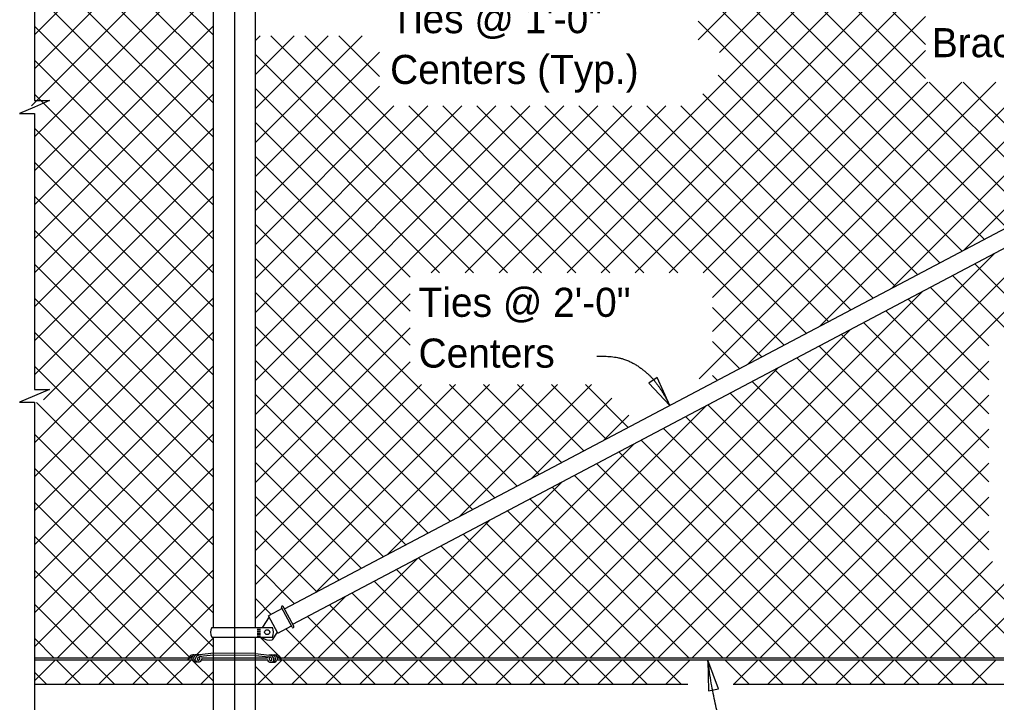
# Model space of a CAD drawing. Extents: x 0.5 to 39.7, y 0.9 to 25.6.
# Drawn here: x 0.72 to 7.49, y 17.01 to 21.74 of the extents above; entities that cross this region are included whole.
import ezdxf

# ---------------------------------------------------------------- set-up
doc = ezdxf.new("R2010")
doc.units = 0
for name, color, linetype in [('CL_Major', 7, 'Continuous'), ('Dimension', 7, 'Continuous'), ('Miscellaneous', 7, 'Continuous'), ('SteelMisc', 7, 'Continuous'), ('SteelMisc_h', 7, 'Continuous'), ('SupstrConc', 7, 'Continuous'), ('TextStructures', 7, 'Continuous')]:
    doc.layers.add(name, color=color, linetype=linetype)

msp = doc.modelspace()

# ---------------------------------------------------------------- linework, layer by layer
at = {"layer": 'CL_Major'}
msp.add_line((2.2062, 25.5043), (2.2062, 14.6639), dxfattribs=at)
at = {"layer": 'Dimension'}
for points in [[(0.8194, 23.1382), (0.8194, 21.1819), (0.9227, 21.1819), (0.8194, 21.1369), (0.716, 21.0919), (0.8194, 21.0919), (0.8194, 20.1983)], [(0.8194, 20.1983), (0.8194, 19.1806), (0.9227, 19.1806), (0.8194, 19.1356), (0.716, 19.0906), (0.8194, 19.0906), (0.8194, 16.8862)], [(0.8194, 17.1362), (0.8194, 15.2854), (0.9227, 15.2854), (0.8194, 15.2404), (0.716, 15.1954), (0.8194, 15.1954), (0.8194, 13.3576)]]:
    msp.add_lwpolyline(points, dxfattribs=at)
for points in [[(5.2237, 19.0693), (5.1367, 19.2617), (5.0782, 19.2224)], [(5.4878, 17.3029), (5.4928, 17.0917), (5.5621, 17.1051)]]:
    msp.add_lwpolyline(points, close=True, dxfattribs=at)
for points in [[(4.7176, 19.4097), (4.8713, 19.4171), (5.0618, 19.3098), (5.1749, 19.1668), (5.2237, 19.0692)], [(6.1508, 16.5088), (5.753, 16.5088), (5.549, 16.8458), (5.4877, 17.3027)]]:
    msp.add_open_spline(points, degree=2, dxfattribs=at)
at = {"layer": 'Miscellaneous'}
for p, q in [((7.2429, 22.9547), (4.2774, 19.9892)), ((7.2492, 20.1396), (4.4341, 22.9547)), ((7.4786, 22.9547), (4.5131, 19.9892)), ((7.4034, 20.2211), (4.6698, 22.9547)), ((7.7143, 22.9547), (4.7488, 19.9892)), ((7.5576, 20.3026), (4.9055, 22.9547)), ((7.95, 22.9547), (4.9845, 19.9892)), ((7.7118, 20.3841), (5.1412, 22.9547)), ((6.9957, 21.336), (5.377, 22.9547)), ((6.7715, 22.9547), (5.4205, 21.6037)), ((7.0072, 22.9547), (5.5678, 21.5153)), ((6.9957, 21.5717), (5.6127, 22.9547)), ((2.0603, 22.8796), (0.8192, 21.6385)), ((2.0603, 21.6353), (0.8192, 22.8764)), ((2.0603, 22.6439), (0.8192, 21.4028)), ((2.0603, 21.3996), (0.8192, 22.6407)), ((2.0603, 22.4082), (0.7982, 21.146)), ((2.0603, 21.1639), (0.8192, 22.405)), ((2.0603, 22.1725), (0.8192, 20.9314)), ((2.0603, 20.9282), (0.8192, 22.1693)), ((2.0603, 21.9368), (0.8192, 20.6957)), ((2.0603, 20.6925), (0.8192, 21.9336)), ((6.9957, 21.7647), (5.2202, 19.9892)), ((2.0603, 21.701), (0.8192, 20.46)), ((2.0603, 20.4568), (0.8192, 21.6979)), ((7.095, 20.0581), (5.4205, 21.7327)), ((2.6187, 21.6304), (2.352, 21.3636)), ((2.383, 21.6304), (2.352, 21.5993)), ((2.8544, 21.6304), (2.352, 21.1279)), ((3.0901, 21.6304), (2.352, 20.8922)), ((4.0998, 19.9892), (2.4587, 21.6304)), ((4.3355, 19.9892), (2.6944, 21.6304)), ((3.2122, 21.3482), (2.9301, 21.6304)), ((3.2122, 21.5167), (2.352, 20.6565)), ((3.8641, 19.9892), (2.352, 21.5013)), ((6.9957, 21.529), (5.4559, 19.9892)), ((2.0603, 21.4653), (0.8192, 20.2243)), ((2.0603, 20.2211), (0.8192, 21.4622)), ((6.9408, 19.9766), (5.559, 21.3585)), ((3.2122, 21.281), (2.352, 20.4208)), ((3.6284, 19.9892), (2.352, 21.2656)), ((7.4843, 21.3105), (5.4275, 19.2537)), ((7.0129, 21.3105), (5.5188, 19.8164)), ((7.2486, 21.3105), (5.5188, 19.5807)), ((7.72, 21.3105), (5.7646, 19.3551)), ((7.9557, 21.3105), (6.2644, 19.6192)), ((8.1914, 21.3105), (6.7643, 19.8834)), ((7.8661, 20.4656), (7.0212, 21.3105)), ((8.0203, 20.5471), (7.2569, 21.3105)), ((8.4271, 21.3105), (7.2641, 20.1475)), ((2.0603, 21.2296), (0.8192, 19.9886)), ((2.0603, 19.9854), (0.8192, 21.2265)), ((6.7866, 19.8952), (5.4525, 21.2292)), ((4.2544, 21.1447), (2.352, 19.2423)), ((3.783, 21.1447), (2.352, 19.7137)), ((3.3116, 21.1447), (2.352, 20.1851)), ((3.5473, 21.1447), (2.352, 19.9494)), ((4.0187, 21.1447), (2.352, 19.478)), ((4.4901, 21.1447), (2.352, 19.0066)), ((4.5712, 19.9892), (3.4157, 21.1447)), ((4.7258, 21.1447), (3.5703, 19.9892)), ((4.8069, 19.9892), (3.6514, 21.1447)), ((4.9615, 21.1447), (3.806, 19.9892)), ((5.0426, 19.9892), (3.8871, 21.1447)), ((5.1972, 21.1447), (4.0417, 19.9892)), ((5.2783, 19.9892), (4.1228, 21.1447)), ((6.0155, 19.4877), (4.3585, 21.1447)), ((6.1697, 19.5692), (4.5942, 21.1447)), ((6.324, 19.6507), (4.8299, 21.1447)), ((6.4782, 19.7322), (5.0656, 21.1447)), ((6.6324, 19.8137), (5.3013, 21.1447)), ((2.0603, 20.9939), (0.8192, 19.7529)), ((3.4233, 19.9586), (2.352, 21.0299)), ((2.0603, 19.7497), (0.8192, 20.9908)), ((3.4233, 19.7229), (2.352, 20.7942)), ((2.0603, 20.7582), (0.8192, 19.5171)), ((2.0603, 19.514), (0.8192, 20.7551)), ((8.4761, 20.6523), (5.1412, 17.3175)), ((2.0603, 20.5225), (0.8192, 19.2814)), ((3.4233, 19.4872), (2.352, 20.5585)), ((2.0603, 19.2783), (0.8192, 20.5194)), ((7.9762, 20.3882), (4.9055, 17.3175)), ((4.165, 18.5098), (2.352, 20.3228)), ((2.0603, 19.0426), (0.8192, 20.2837)), ((2.0603, 20.2868), (0.8817, 19.1083)), ((7.4764, 20.1241), (4.6698, 17.3175)), ((2.0603, 20.0511), (0.8192, 18.81)), ((2.0603, 18.8069), (0.8192, 20.048)), ((4.0108, 18.4283), (2.352, 20.0871)), ((7.8655, 19.5233), (7.3379, 20.0509)), ((7.6298, 19.5233), (7.1837, 19.9694)), ((3.8566, 18.3468), (2.352, 19.8514)), ((6.9765, 19.8599), (4.4341, 17.3175)), ((7.4353, 19.4821), (7.0295, 19.8879)), ((2.0603, 19.8154), (0.8192, 18.5743)), ((2.0603, 18.5712), (0.8192, 19.8123)), ((3.4233, 19.8423), (2.352, 18.7709)), ((7.4353, 19.2464), (6.8753, 19.8064)), ((5.8613, 19.4062), (5.5188, 19.7488)), ((7.4353, 19.0107), (6.7211, 19.7249)), ((7.4353, 18.775), (6.5669, 19.6435)), ((2.0603, 19.5797), (0.8192, 18.3386)), ((2.0603, 18.3355), (0.8192, 19.5766)), ((3.7024, 18.2653), (2.352, 19.6157)), ((3.4233, 19.6066), (2.352, 18.5352)), ((6.4767, 19.5958), (4.1984, 17.3175)), ((5.7071, 19.3247), (5.5188, 19.5131)), ((7.4353, 18.5393), (6.4127, 19.562)), ((7.4353, 18.3036), (6.2585, 19.4805)), ((3.5482, 18.1838), (2.352, 19.38)), ((3.4233, 19.3709), (2.352, 18.2995)), ((7.4353, 19.3759), (5.377, 17.3175)), ((7.4353, 18.0679), (6.1042, 19.399)), ((2.0603, 19.344), (0.8192, 18.1029)), ((2.0603, 18.0998), (0.8192, 19.3409)), ((5.9769, 19.3317), (3.9627, 17.3175)), ((7.95, 17.3175), (5.95, 19.3175)), ((5.5529, 19.2432), (5.5188, 19.2774)), ((7.7143, 17.3175), (5.7958, 19.236)), ((3.7384, 19.2146), (2.352, 17.8281)), ((3.5027, 19.2146), (2.352, 18.0638)), ((3.9741, 19.2146), (2.352, 17.5924)), ((4.2098, 19.2146), (2.7654, 17.7701)), ((4.4455, 19.2146), (3.2653, 18.0343)), ((4.3192, 18.5913), (3.6959, 19.2146)), ((4.6812, 19.2146), (3.7651, 18.2985)), ((4.4734, 18.6728), (3.9317, 19.2146)), ((4.6277, 18.7543), (4.1674, 19.2146)), ((4.7819, 18.8357), (4.4031, 19.2146)), ((4.9361, 18.9172), (4.6388, 19.2146)), ((2.0603, 19.1083), (0.8192, 17.8672)), ((3.394, 18.1023), (2.352, 19.1443)), ((4.8227, 19.1203), (4.265, 18.5626)), ((7.4353, 19.1402), (5.6127, 17.3175)), ((7.4786, 17.3175), (5.6416, 19.1545)), ((2.0603, 17.8641), (0.8339, 19.0905)), ((5.477, 19.0675), (3.727, 17.3175)), ((7.2429, 17.3175), (5.4874, 19.073)), ((4.9405, 19.0024), (4.7648, 18.8268)), ((7.0072, 17.3175), (5.3332, 18.9915)), ((3.2398, 18.0208), (2.352, 18.9086)), ((6.7715, 17.3175), (5.179, 18.91)), ((7.4353, 18.9045), (5.8484, 17.3175)), ((2.0603, 18.8726), (0.8192, 17.6315)), ((2.0603, 17.6284), (0.8192, 18.8695)), ((6.5358, 17.3175), (5.0248, 18.8285)), ((4.9772, 18.8034), (3.4913, 17.3175)), ((6.3001, 17.3175), (4.8706, 18.747)), ((2.0603, 18.6369), (0.8192, 17.3958)), ((2.0603, 17.3927), (0.8192, 18.6338)), ((3.0856, 17.9393), (2.352, 18.6729)), ((6.0644, 17.3175), (4.7163, 18.6656)), ((7.4353, 18.6688), (6.0841, 17.3175)), ((5.8287, 17.3175), (4.5621, 18.5841)), ((4.4774, 18.5393), (3.2556, 17.3175)), ((5.593, 17.3175), (4.4079, 18.5026)), ((2.9314, 17.8578), (2.352, 18.4372)), ((5.3573, 17.3175), (4.2537, 18.4211)), ((7.4353, 18.4331), (6.3198, 17.3175)), ((1.8909, 17.3264), (0.8192, 18.3981)), ((2.0603, 18.4012), (0.9766, 17.3175)), ((5.1216, 17.3175), (4.0995, 18.3396)), ((3.9775, 18.2751), (3.0199, 17.3175)), ((4.8859, 17.3175), (3.9453, 18.2581)), ((1.6641, 17.3175), (0.8192, 18.1624)), ((2.0603, 18.1655), (1.2123, 17.3175)), ((2.7771, 17.7763), (2.352, 18.2015)), ((4.6502, 17.3175), (3.7911, 18.1766)), ((7.4353, 18.1974), (6.5555, 17.3175)), ((4.4145, 17.3175), (3.6369, 18.0951)), ((2.6229, 17.6948), (2.352, 17.9658)), ((3.4777, 18.011), (2.7842, 17.3175)), ((4.1788, 17.3175), (3.4827, 18.0136)), ((7.4598, 17.9862), (6.7912, 17.3175)), ((7.6955, 17.9862), (7.0269, 17.3175)), ((7.9312, 17.9862), (7.2626, 17.3175)), ((1.4284, 17.3175), (0.8192, 17.9267)), ((2.0603, 17.9298), (1.448, 17.3175)), ((3.943, 17.3175), (3.3285, 17.9321)), ((3.7073, 17.3175), (3.1742, 17.8506)), ((2.9778, 17.7469), (2.5485, 17.3175)), ((3.4716, 17.3175), (3.02, 17.7692)), ((1.1927, 17.3175), (0.8192, 17.691)), ((2.0603, 17.6941), (1.6837, 17.3175)), ((2.4612, 17.6209), (2.352, 17.7301)), ((3.2359, 17.3175), (2.8658, 17.6877)), ((3.0002, 17.3175), (2.7116, 17.6062)), ((2.7645, 17.3175), (2.5621, 17.52)), ((0.957, 17.3175), (0.8192, 17.4553)), ((2.0603, 17.4584), (1.9429, 17.341)), ((2.5129, 17.3335), (2.3833, 17.4631)), ((0.9619, 17.3028), (0.8192, 17.1601)), ((1.1384, 17.1361), (0.9717, 17.3028)), ((1.1976, 17.3028), (1.0309, 17.1361)), ((1.3741, 17.1361), (1.2074, 17.3028)), ((1.4333, 17.3028), (1.2666, 17.1361)), ((1.6098, 17.1361), (1.4431, 17.3028)), ((1.669, 17.3028), (1.5023, 17.1361)), ((1.8455, 17.1361), (1.6788, 17.3028)), ((1.9047, 17.3028), (1.738, 17.1361)), ((2.0603, 17.157), (1.922, 17.2953)), ((2.5338, 17.3028), (2.3671, 17.1361)), ((2.5288, 17.3175), (2.5253, 17.3211)), ((2.7103, 17.1361), (2.5436, 17.3028)), ((2.7695, 17.3028), (2.6028, 17.1361)), ((2.946, 17.1361), (2.7793, 17.3028)), ((3.0052, 17.3028), (2.8385, 17.1361)), ((3.1817, 17.1361), (3.015, 17.3028)), ((3.2409, 17.3028), (3.0742, 17.1361)), ((3.4174, 17.1361), (3.2507, 17.3028)), ((3.4766, 17.3028), (3.3099, 17.1361)), ((3.6531, 17.1361), (3.4864, 17.3028)), ((3.7123, 17.3028), (3.5456, 17.1361)), ((3.8888, 17.1361), (3.7221, 17.3028)), ((3.948, 17.3028), (3.7813, 17.1361)), ((4.1245, 17.1361), (3.9578, 17.3028)), ((4.1837, 17.3028), (4.017, 17.1361)), ((4.3602, 17.1361), (4.1935, 17.3028)), ((4.4194, 17.3028), (4.2527, 17.1361)), ((4.5959, 17.1361), (4.4292, 17.3028)), ((4.6551, 17.3028), (4.4884, 17.1361)), ((4.8316, 17.1361), (4.6649, 17.3028)), ((4.8908, 17.3028), (4.7241, 17.1361)), ((5.0673, 17.1361), (4.9006, 17.3028)), ((5.1265, 17.3028), (4.9598, 17.1361)), ((5.303, 17.1361), (5.1363, 17.3028)), ((5.3622, 17.3028), (5.1955, 17.1361)), ((5.7744, 17.1361), (5.6077, 17.3028)), ((5.8336, 17.3028), (5.6669, 17.1361)), ((6.0101, 17.1361), (5.8434, 17.3028)), ((6.0693, 17.3028), (5.9026, 17.1361)), ((6.2458, 17.1361), (6.0791, 17.3028)), ((6.305, 17.3028), (6.1383, 17.1361)), ((6.4815, 17.1361), (6.3148, 17.3028)), ((6.5407, 17.3028), (6.374, 17.1361)), ((6.7172, 17.1361), (6.5505, 17.3028)), ((6.7764, 17.3028), (6.6097, 17.1361)), ((6.9529, 17.1361), (6.7862, 17.3028)), ((7.0121, 17.3028), (6.8455, 17.1361)), ((7.1886, 17.1361), (7.0219, 17.3028)), ((7.2478, 17.3028), (7.0812, 17.1361)), ((7.4243, 17.1361), (7.2576, 17.3028)), ((7.4835, 17.3028), (7.3169, 17.1361)), ((0.9027, 17.1361), (0.8192, 17.2196)), ((2.0571, 17.2195), (1.9737, 17.1361)), ((2.4746, 17.1361), (2.352, 17.2587))]:
    msp.add_line(p, q, dxfattribs=at)
at = {"layer": 'SteelMisc'}
for p, q in [((2.0603, 17.5309), (2.0603, 23.1761)), ((2.352, 17.5309), (2.352, 23.1761)), ((2.5536, 17.6582), (11.8032, 22.5462)), ((2.6095, 17.5522), (11.8592, 22.4401)), ((2.5369, 17.6609), (2.4426, 17.6111)), ((2.5063, 17.4905), (2.4426, 17.6111)), ((2.6052, 17.5317), (2.5328, 17.6688)), ((2.6171, 17.538), (2.5446, 17.6751)), ((2.4468, 17.6031), (2.3999, 17.5313)), ((2.5063, 17.4905), (2.6006, 17.5404)), ((2.049, 17.5309), (2.4687, 17.5309)), ((2.3864, 17.5246), (2.3629, 17.5246)), ((2.3864, 17.5148), (2.3629, 17.5148)), ((2.3864, 17.5031), (2.3629, 17.5031)), ((2.3864, 17.4913), (2.3629, 17.4913)), ((2.3864, 17.4805), (2.3629, 17.4805)), ((2.5029, 17.4971), (2.4681, 17.4439)), ((2.0491, 17.4631), (2.4687, 17.4631)), ((2.0603, 16.801), (2.0603, 17.4631)), ((2.352, 16.801), (2.352, 17.4631)), ((2.3864, 17.4709), (2.3629, 17.4709)), ((2.0608, 17.3518), (1.9665, 17.3407)), ((2.0608, 17.3373), (1.9687, 17.3279)), ((2.352, 17.3501), (2.0608, 17.3518)), ((2.352, 17.3356), (2.0608, 17.3373)), ((2.352, 17.3501), (2.4469, 17.339)), ((1.8859, 17.3175), (0.8192, 17.3175)), ((1.9154, 17.3028), (0.8192, 17.3028)), ((1.9096, 17.3175), (1.8943, 17.3175)), ((2.0603, 17.3028), (1.9773, 17.3028)), ((2.0603, 17.3175), (1.9799, 17.3175)), ((2.352, 17.3356), (2.4446, 17.3261)), ((2.4342, 17.3175), (2.352, 17.3175)), ((2.4356, 17.3028), (2.352, 17.3028)), ((11.8982, 17.3028), (2.5005, 17.3028)), ((2.5172, 17.3175), (2.5041, 17.3175)), ((11.8969, 17.3175), (2.5271, 17.3175))]:
    msp.add_line(p, q, dxfattribs=at)
for centre, start, end in [((2.5385, 17.6721), 27.85098, 207.85098), ((2.611, 17.5349), 207.85098, 27.85098)]:
    msp.add_arc(centre, 0.00673, start, end, dxfattribs=at)
for centre, major_axis, ratio, start_param, end_param in [((2.1181, 17.4971), (-0.0776, 0), 0.957868, 5.811591, 6.758603), ((2.3995, 17.4972), (0.0776, 0), 0.957868, 5.810211, 6.75616), ((2.4515, 17.5123), (-0.0647, -0.0342), 0.957868, 0.271397, 1.331255), ((1.9209, 17.305), (0.0373, 0), 0.957868, 1.486836, 3.108042), ((1.9333, 17.3195), (0.023, 0), 0.957868, 1.29026, 2.970541), ((1.9521, 17.3141), (0.0295, 0), 0.957868, 1.220941, 4.039556), ((1.9656, 17.3159), (-0.0303, -0.0108), 0.724765, 4.35367, 6.324556), ((2.4482, 17.3142), (0.0303, -0.0108), 0.724765, 6.241815, 8.212701), ((2.4617, 17.3124), (-0.0295, 0), 0.957868, 2.243629, 5.062245), ((2.4804, 17.3177), (-0.023, 0), 0.957868, 3.312645, 4.992926), ((2.4929, 17.3033), (-0.0373, 0), 0.957868, 3.175144, 4.79635), ((1.942, 17.2653), (-0.0724, 0), 0.957868, 5.162149, 5.652106), ((1.9345, 17.317), (-0.0249, 0), 0.957868, 6.009018, 7.089857), ((1.9359, 17.313), (0.0231, 0), 0.957868, 3.779554, 4.879821), ((1.942, 17.3073), (0.0206, -0.0021), 0.798607, 4.32653, 5.220153), ((1.9554, 17.3073), (0.0206, -0.0021), 0.798607, 3.333154, 5.220153), ((1.9623, 17.3119), (-0.0139, 0), 0.957868, 5.22362, 6.905413), ((1.9566, 17.3095), (-0.00795, 0), 0.957868, 6.140374, 9.314262), ((1.9706, 17.303), (-0.0259, 0), 0.957868, 4.777514, 5.62749), ((1.9549, 17.3153), (0.0119, 0), 0.957868, 5.725876, 7.416677), ((1.9481, 17.3261), (0.0391, 0), 0.957868, 5.082588, 5.41974), ((1.9549, 17.3153), (0.0119, 0), 0.957868, 5.639684, 5.723117), ((1.9551, 17.314), (0.0251, 0), 0.957868, 5.531357, 6.227833), ((1.9551, 17.314), (0.0251, 0), 0.957868, 0.407687, 0.609214), ((2.4586, 17.3123), (-0.0251, 0), 0.957868, 0.055352, 0.751829), ((2.4586, 17.3123), (-0.0251, 0), 0.957868, 5.673972, 5.875498), ((2.4657, 17.3243), (-0.0391, 0), 0.957868, 0.863445, 1.200597), ((2.4431, 17.3012), (0.0259, 0), 0.957868, 0.655696, 1.505671), ((2.4589, 17.3135), (-0.0119, 0), 0.957868, 5.149694, 6.840495), ((2.4589, 17.3135), (-0.0119, 0), 0.957868, 0.560069, 0.643501), ((2.4572, 17.3077), (0.00795, 0), 0.957868, 3.252108, 6.425997), ((2.4583, 17.3055), (-0.0206, -0.0021), 0.798607, 1.063032, 2.950031), ((2.4515, 17.3101), (0.0139, 0), 0.957868, 5.660958, 7.342751), ((2.4718, 17.3055), (-0.0206, -0.0021), 0.798607, 1.063032, 1.956656), ((2.4779, 17.3112), (-0.0231, 0), 0.957868, 1.403365, 2.503632), ((2.4793, 17.3152), (0.0249, 0), 0.957868, 5.476514, 6.557353), ((2.4718, 17.2636), (0.0724, 0), 0.957868, 0.631079, 1.121037)]:
    msp.add_ellipse(centre, major_axis=major_axis, ratio=ratio, start_param=start_param, end_param=end_param, dxfattribs=at)
msp.add_ellipse((2.4328, 17.4976), major_axis=(-0.0178, 0), ratio=0.957868, dxfattribs=at)
at = {"layer": 'SteelMisc_h'}
for p, q in [((2.352, 17.3175), (2.0603, 17.3175)), ((2.352, 17.3028), (2.0603, 17.3028))]:
    msp.add_line(p, q, dxfattribs=at)
at = {"layer": 'SupstrConc'}
for p, q in [((0.8193, 17.1361), (5.3495, 17.1361)), ((5.6627, 17.1361), (12.0604, 17.1361))]:
    msp.add_line(p, q, dxfattribs=at)

# ---------------------------------------------------------------- texts
at = {"layer": 'TextStructures'}
for s, p in [('Ties @ 1\'-0" ', (3.285, 21.6493)), ('Brace Rail', (7.0402, 21.4829)), ('Centers (Typ.)', (3.285, 21.2973)), ('Ties @ 2\'-0" ', (3.4821, 19.6831)), ('Centers', (3.4821, 19.3311))]:
    msp.add_text(s, height=0.2016, dxfattribs=at).set_placement(p)

doc.saveas('drawing.dxf')
